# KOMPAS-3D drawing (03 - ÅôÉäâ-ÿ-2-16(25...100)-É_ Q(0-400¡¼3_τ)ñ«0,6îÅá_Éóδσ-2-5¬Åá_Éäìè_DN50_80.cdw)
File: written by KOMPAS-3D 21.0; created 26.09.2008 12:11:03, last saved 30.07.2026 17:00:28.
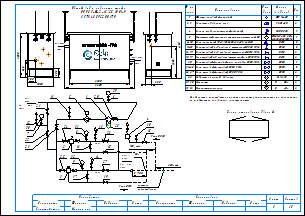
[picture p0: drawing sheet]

Sheets 1-2: A3, landscape

Document properties: Наименование: Макро:21; Автор: RaskoAdmin; Форматы листов документа: 2xA3; Полное имя файла: \\UR38nt01\Departments\КТО\КБ ПУРДГ\Заявки\Прайс-лист на типовые шкафы ГРПШ\ПУРДГ_стандарт_30_04_2026\ПУРДГ с РДНК\ПУРДГ-Ш-2-16(25...100)-Р_ Q(0-400нм3_ч)до0,6МПа_Рвых-2-5кПа_РДНК_DN50_80.cdw

Title block, sheet 1: Наименование: Пункт учета газа / ПУГ-Ш-400-Р / ЛГТИ.485922.001ТУ; designation: ЛГТИ.03.4411141; sheet number: 1; Количество листов документа: 2; organisation: ООО "ЭЛЬСТЕР Газэлектроника"; Форматы листов документа: A3; stored path: C:\Рабочие документы\Компас\ПУГ\Схема.cdw; Разработал: Устинов; Проверил: Кошкин; Утвердил: Кошкин
Title block, sheet 2: sheet number: 2; stored path: D:\Рабочие документы\Заявки\ПУРДГ\ПУРДГ-ШУЭО-2-100-Р 4411220.cdw; designation, second copy: ЛГТИ.03.4411141-

Views: Вид 1, Вид 2
Referenced files: wcvoit.frw
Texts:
  Normal
  № на
  схеме
  Усл.
  обозн.
  Марка
  (модель)
  Кол.
  Фильтр газовый фланцевый
  ФГ 16-50
  Регулятор давления газа
  РДНК-50
  Клапан предохранительный сбросной
  КПС DN20
  Измерительный комплекс с ротационным счетчиком Ду50
  СГ-ЭК-Р-(0,2...2,0)-
  Кран кнопочный VE-РАСКО-НЗ-1,6-G1/2-М20
  DN15
  Кран шаровой "под приварку" штуцерный DN20 PN16
  DN20
  Кран шаровой "под приварку" штуцерный DN15 PN16
  Кран шаровой "под приварку" штуцерный п/п DN15 PN16
  Кран шаровой фланцевый с мех. приводом DN50 PN16
  Кран шаровой фланцевый DN50 PN16
  Кран шаровой фланцевый DN80 PN16
  DN50
  DN80
  Индикатор перепада давления
  Манометр
  Манометр-напоромер
  Delta 15
  0...     МПа
  0...     кПа
  Общий вид и габариты шкафа
  ПУРДГ-Ш-2-16(25...100)-Р
  Выход газа
  Вход газа
  logo-rasko-ge.png
  DN 1
  местное
  сопротивление
  Римп DN15
  Римп DN20
  Выход
  газа
  Р=     кПа
  Вход
  Р=       МПа
  PDI
  Схема открывания дверей
  Предприятие изготовитель может заменять комплектующие на аналогичные,
  не ухудшающие заявленных характеристик.
  Должность
  Конструктор
  Фамилия
  Подпись
  Дата
  Согласовано
  Максимкин
  Лист
  Листов
  POLYLINE_STYLE_0.18_RGB_0_0_0
  POLYLINE_STYLE_0.50_RGB_0_0_0
  POLYLINE_STYLE_0.34_RGB_0_0_0
  PHANTOM_RGB_0_0_0_SC_1_THICK_0.18
  K5LT_THIN_RGB_0_0_0_THICK_0.18
  K5LT32769_RGB_0_0_0_THICK_0.18
  K5LT12_RGB_0_0_0_SC_1_THICK_0.18
  K5LT_DASHED_RGB_0_0_0_SC_1_THICK_0.18
  ACISOTGL_RGB_0_0_0_SC_0.8_THICK_0.25
  CONTINUOUS_RGB_0_127_31_THICK_0.3
  CONTINUOUS_RGB_0_0_255_THICK_0.35
  CONTINUOUS_RGB_255_0_0_THICK_0.35
  POLYLINE_STYLE_0.25_RGB_0_0_0
  CONTINUOUS_RGB_0_0_0_THICK_0.5
  POLYLINE_STYLE_0.35_RGB_0_0_255
  CONTINUOUS_RGB_0_0_0_THICK_0.4
  CONTINUOUS_RGB_0_0_0_THICK_0.35
  НЕВИДИМАЯ_RGB_0_0_0_SC_0.3_THICK_0.25
  СONTINUOUS_RGB_0_0_0_THICK_0.25
  ОСЕВАЯ2_RGB_248_153_30_SC_0.3_THICK_0.25
  Без оформления
Dimensions and other numbers on the sheet: 1; 2, 3; 2; 4; 5; 6-10; 11-15; 16, 17; 18, 19; 20; 21-25; 26, 27; 28; 29, 30; 31, 32; 1500; 250; 300; 1050; 550; 305; 2300; 4130; 2000; 2600; 5,,,7DN 1; 7; 30; 12; 21; 22; 23; 11; 6; 29; 24; 31; 8; 16; 13; 26; 18; 10; 15; 25; 32; 9; 3; 17; 14; 27; 19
